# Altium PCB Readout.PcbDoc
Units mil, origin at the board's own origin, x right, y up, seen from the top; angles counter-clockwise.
Board outline 2000 x 2300 mil, 6 copper layers (Top Layer, VCC, GND, VEE, GND 2, Bottom Layer), stack 32.112 mil thick; 55 components, 25 nets, 158 pads, 32 vias.
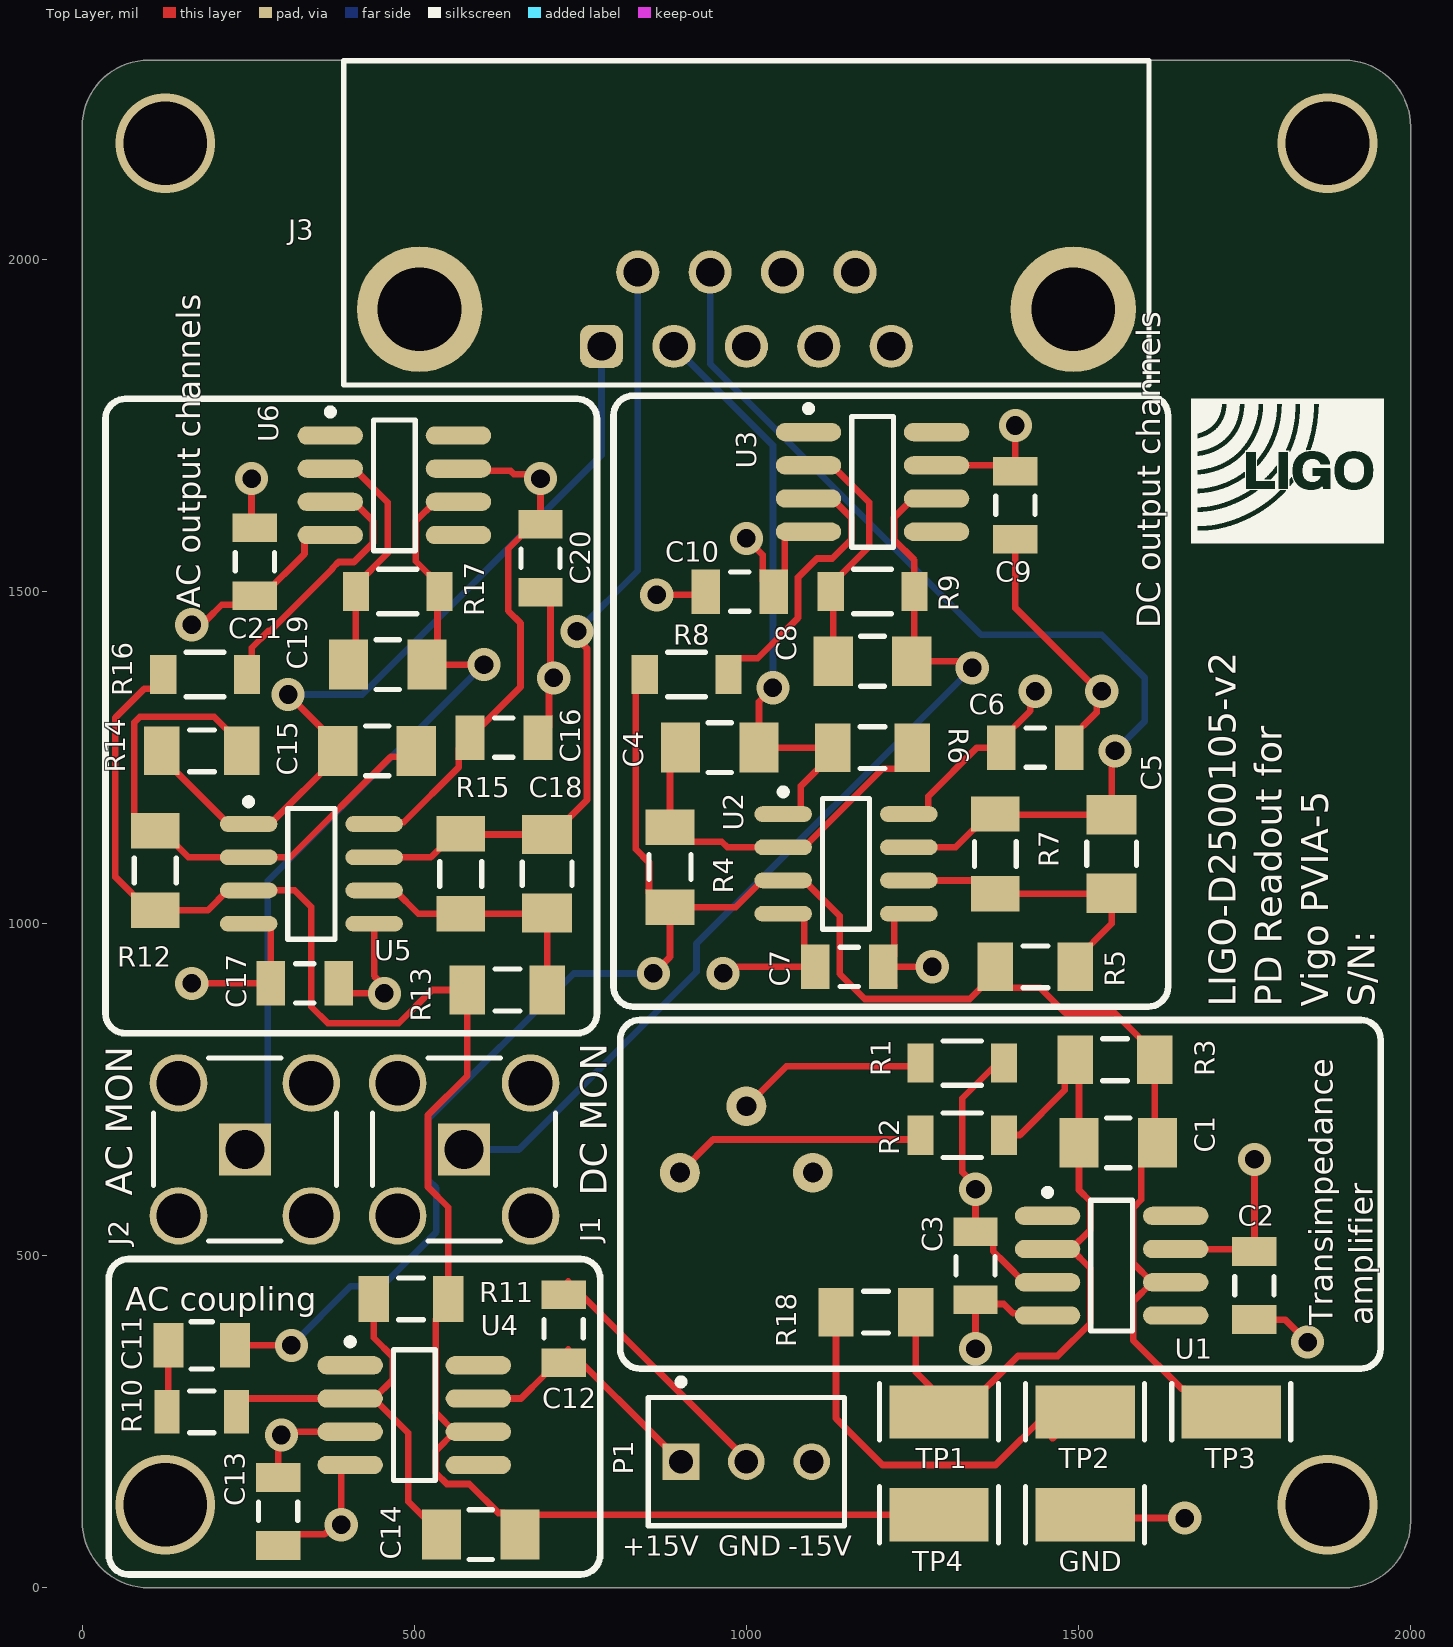
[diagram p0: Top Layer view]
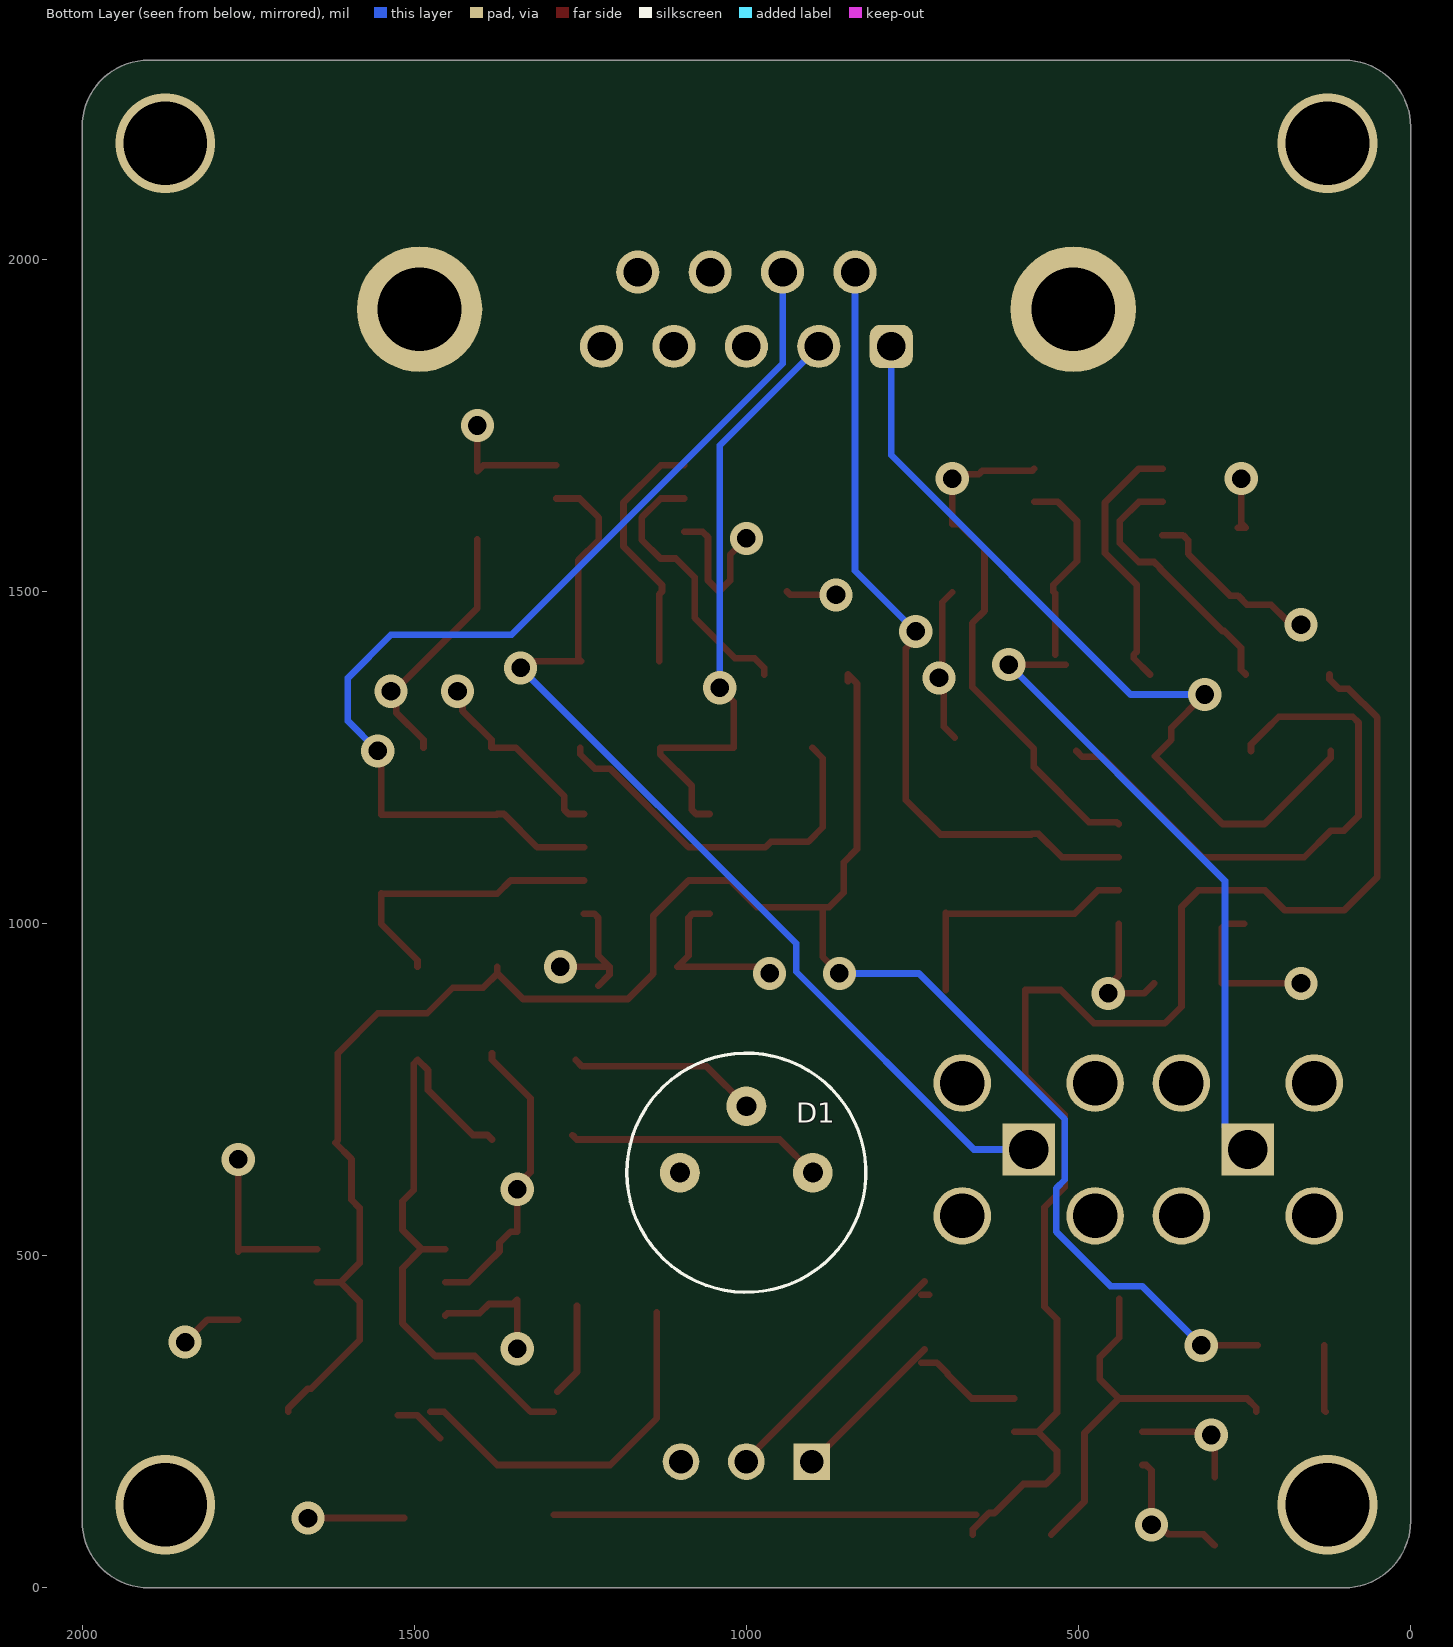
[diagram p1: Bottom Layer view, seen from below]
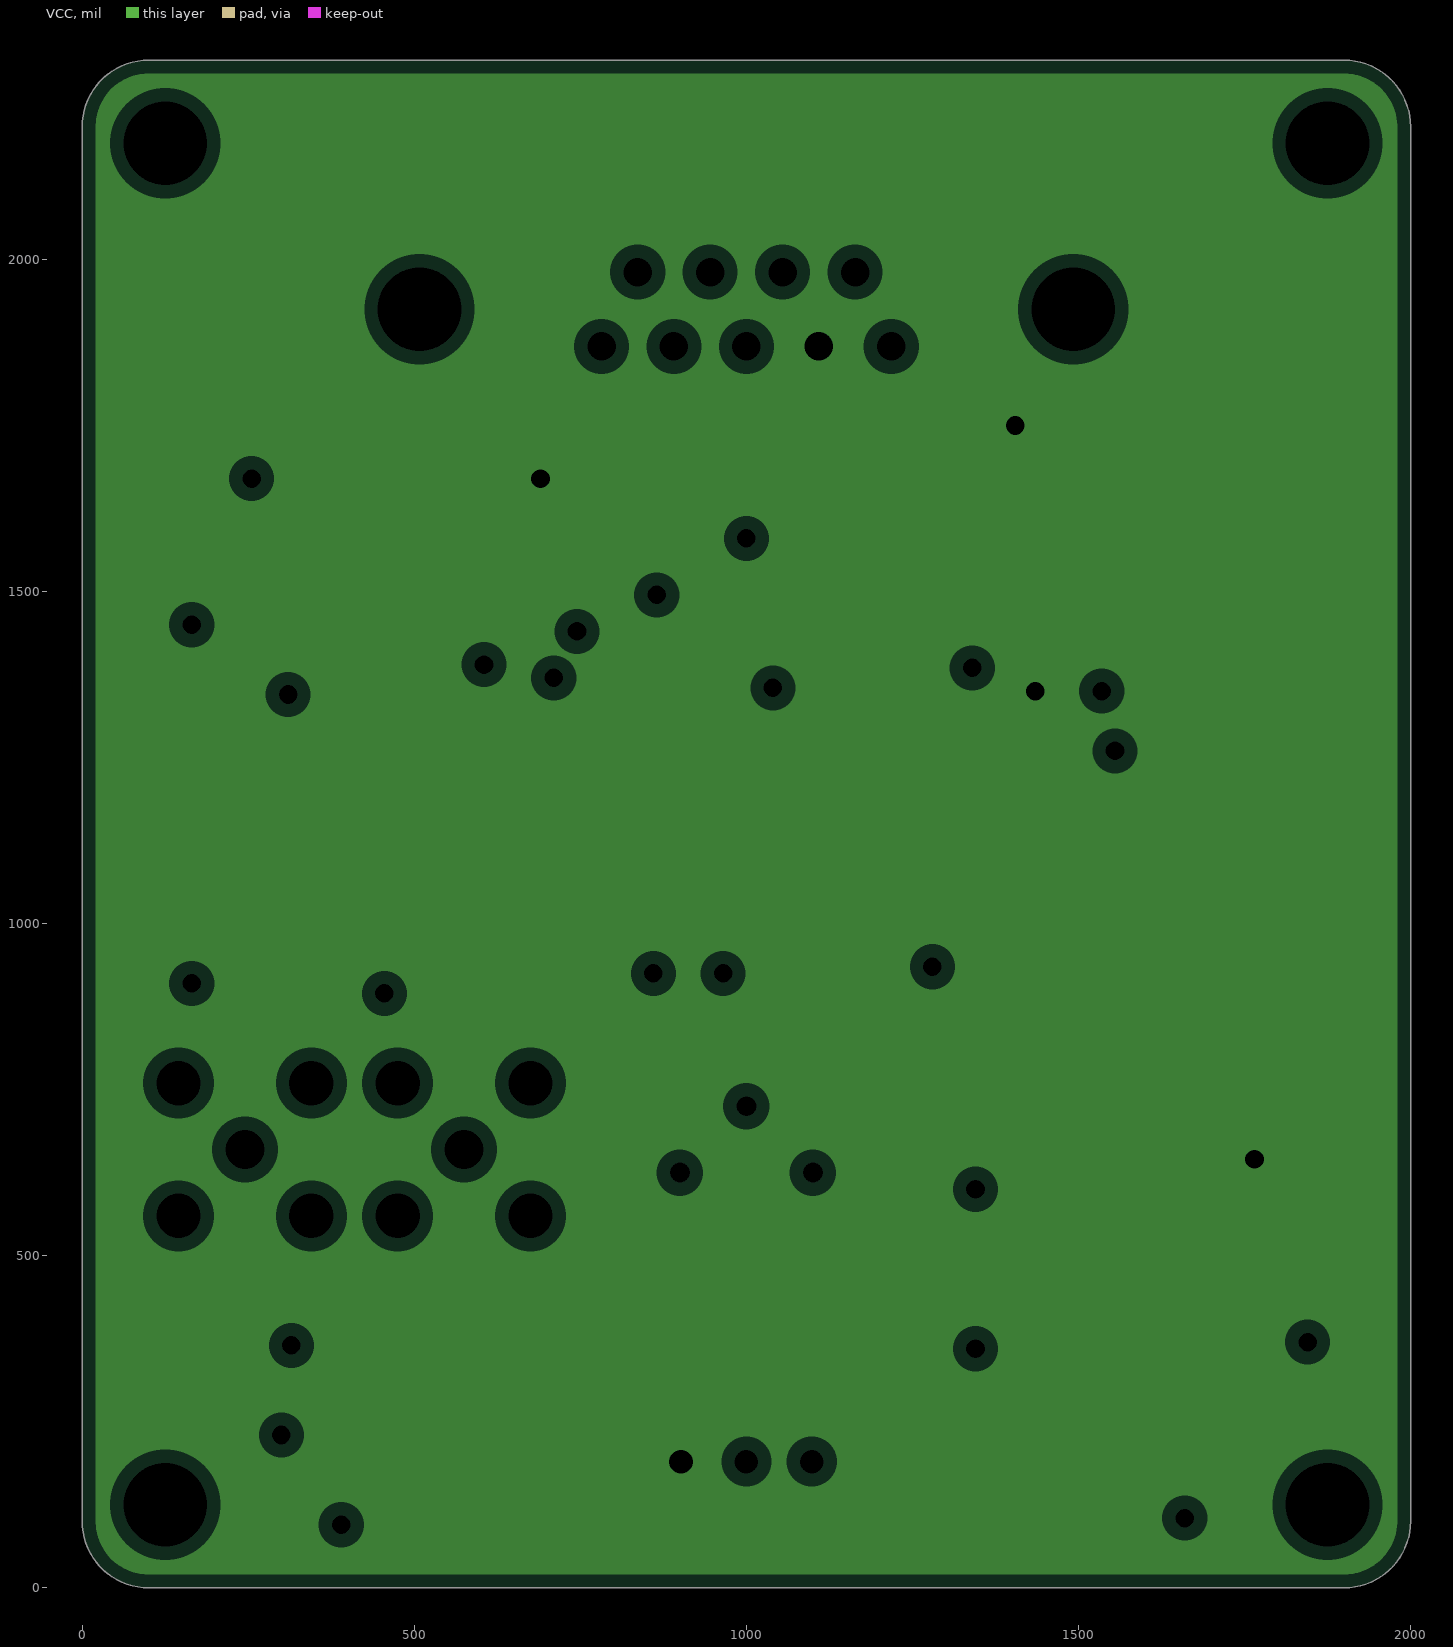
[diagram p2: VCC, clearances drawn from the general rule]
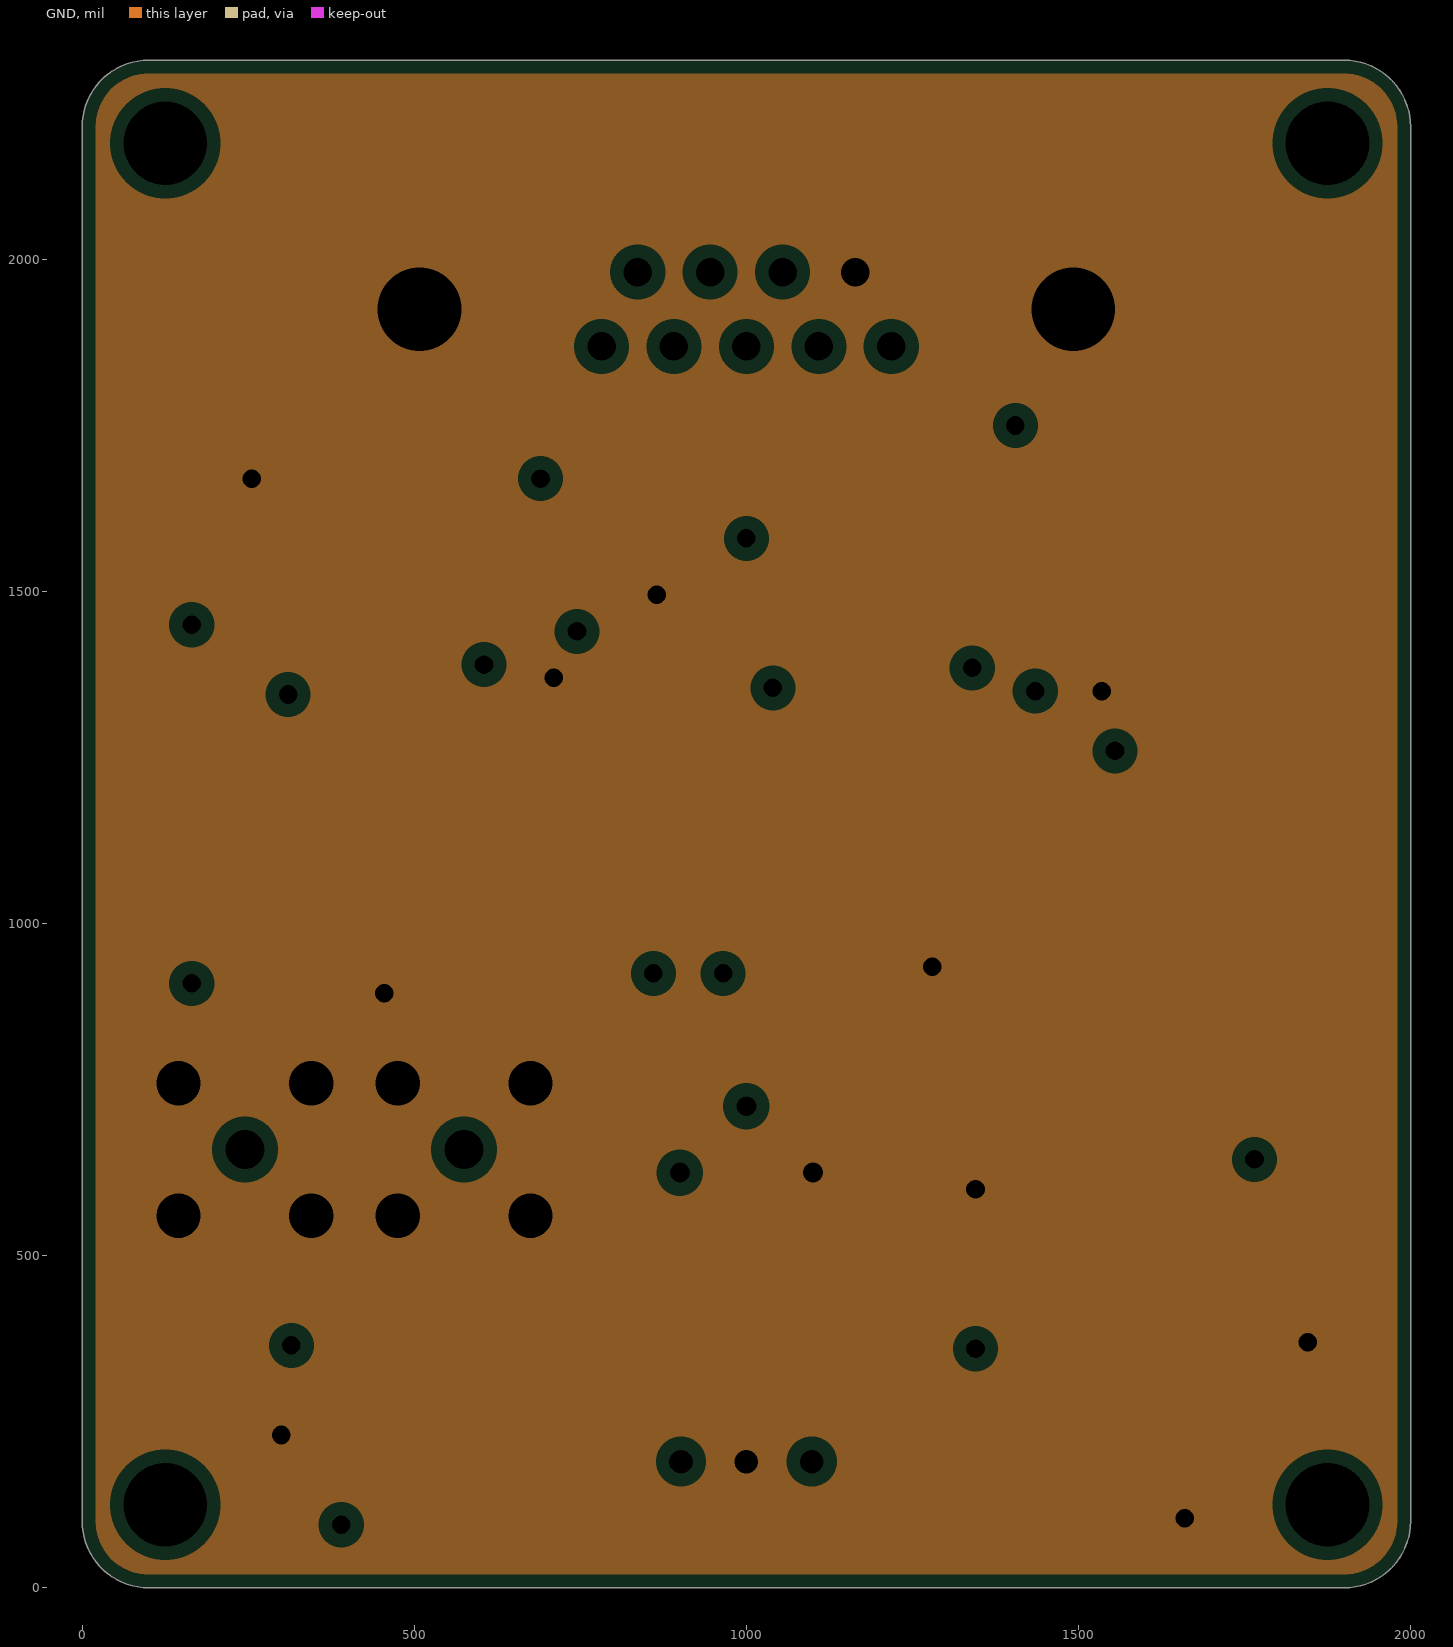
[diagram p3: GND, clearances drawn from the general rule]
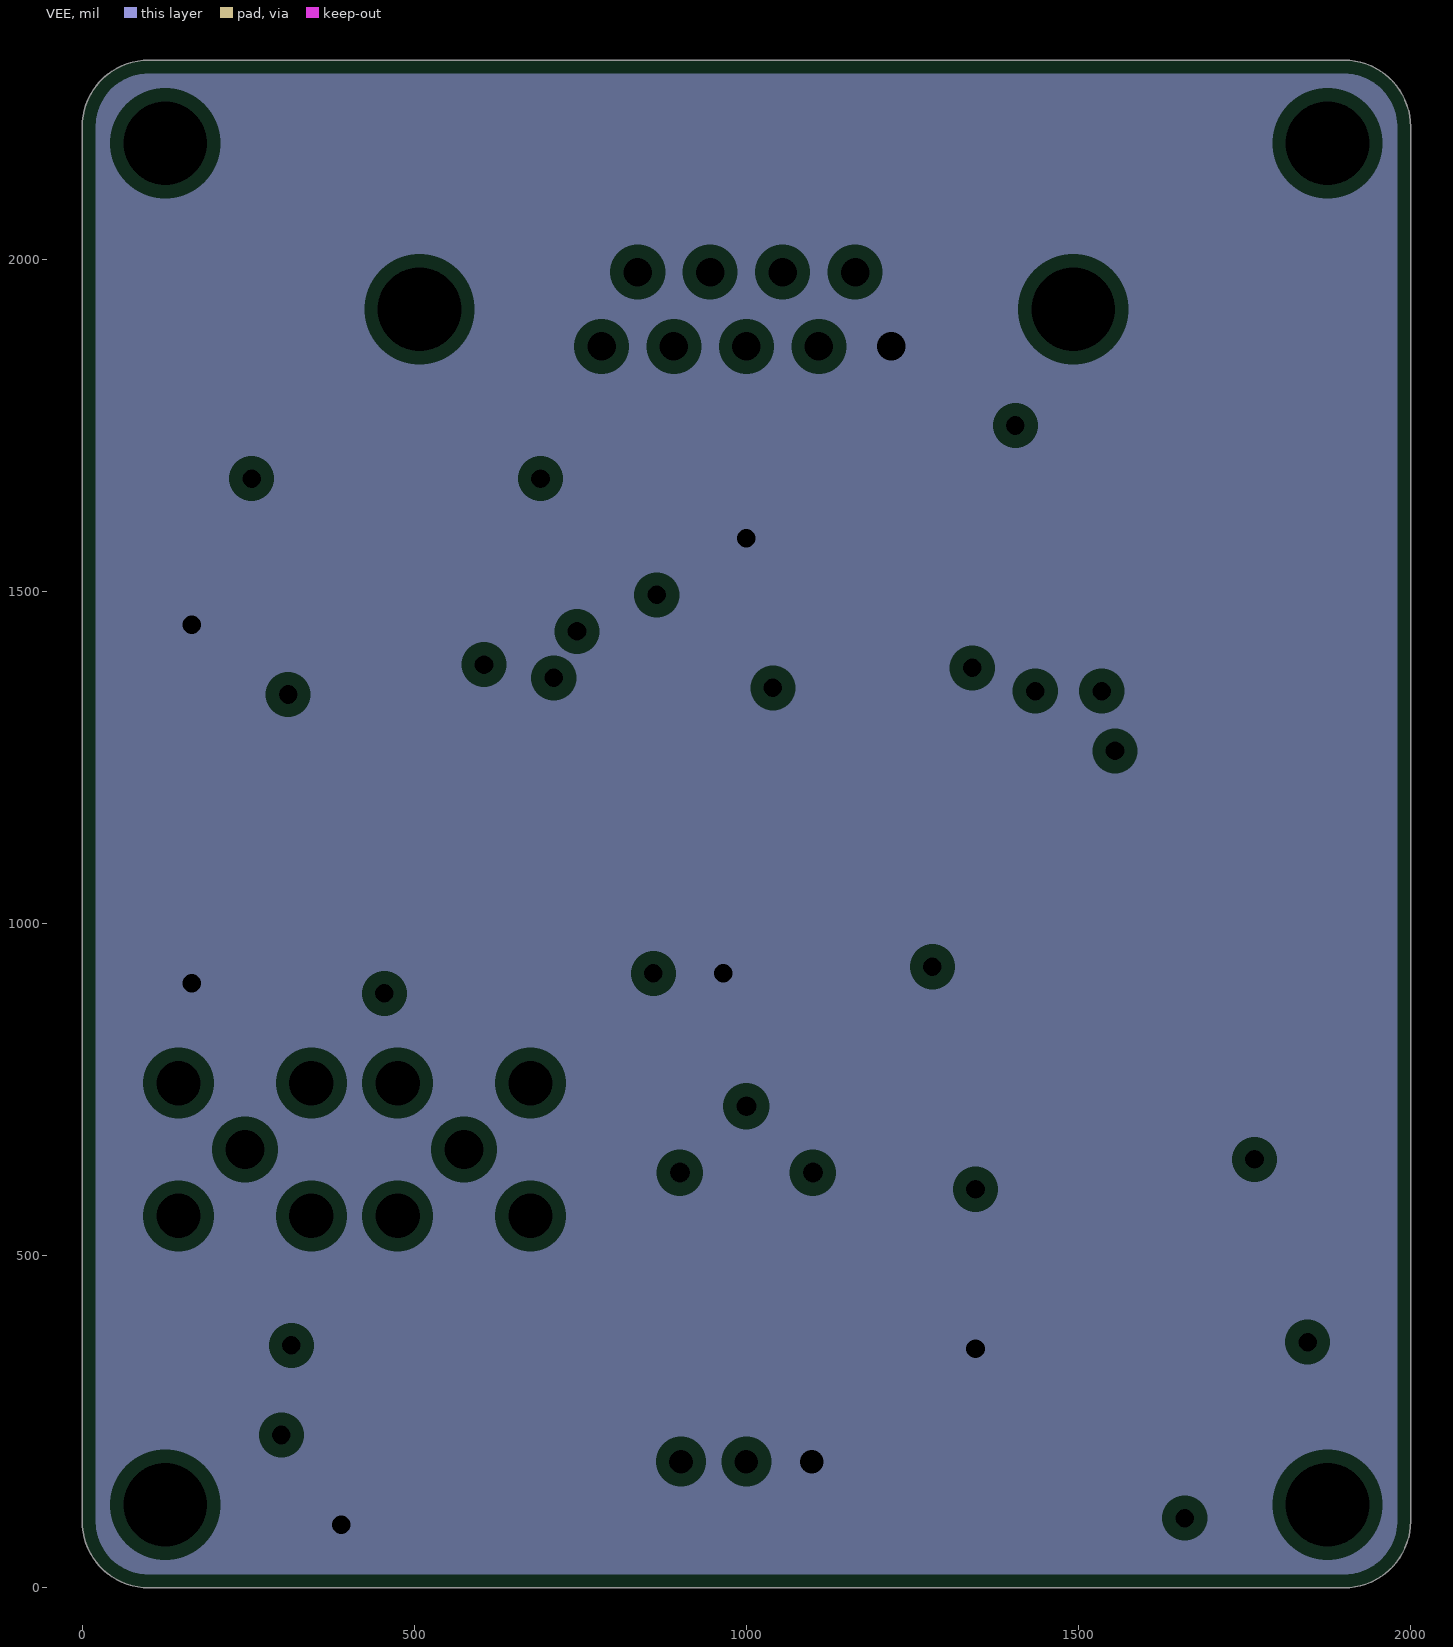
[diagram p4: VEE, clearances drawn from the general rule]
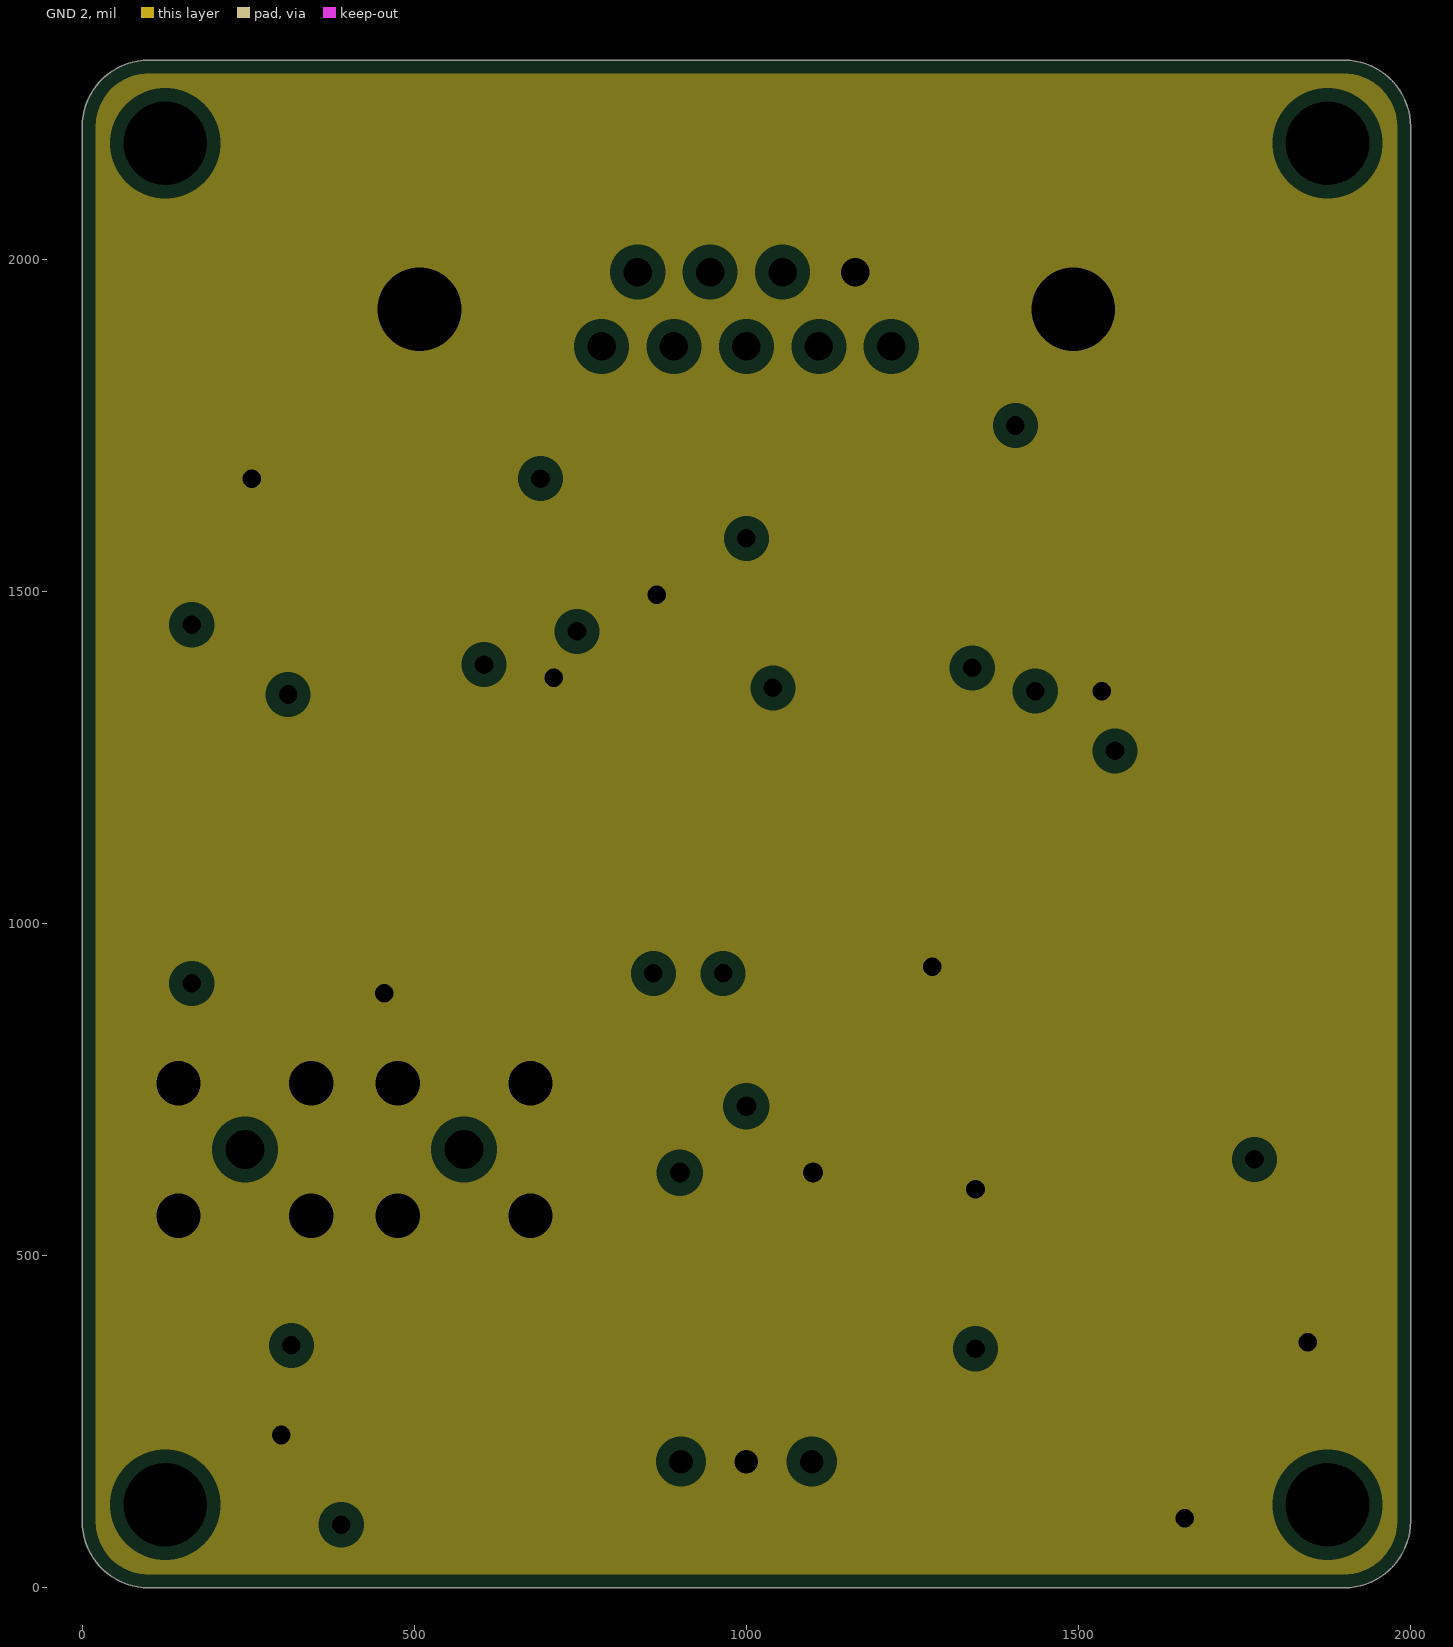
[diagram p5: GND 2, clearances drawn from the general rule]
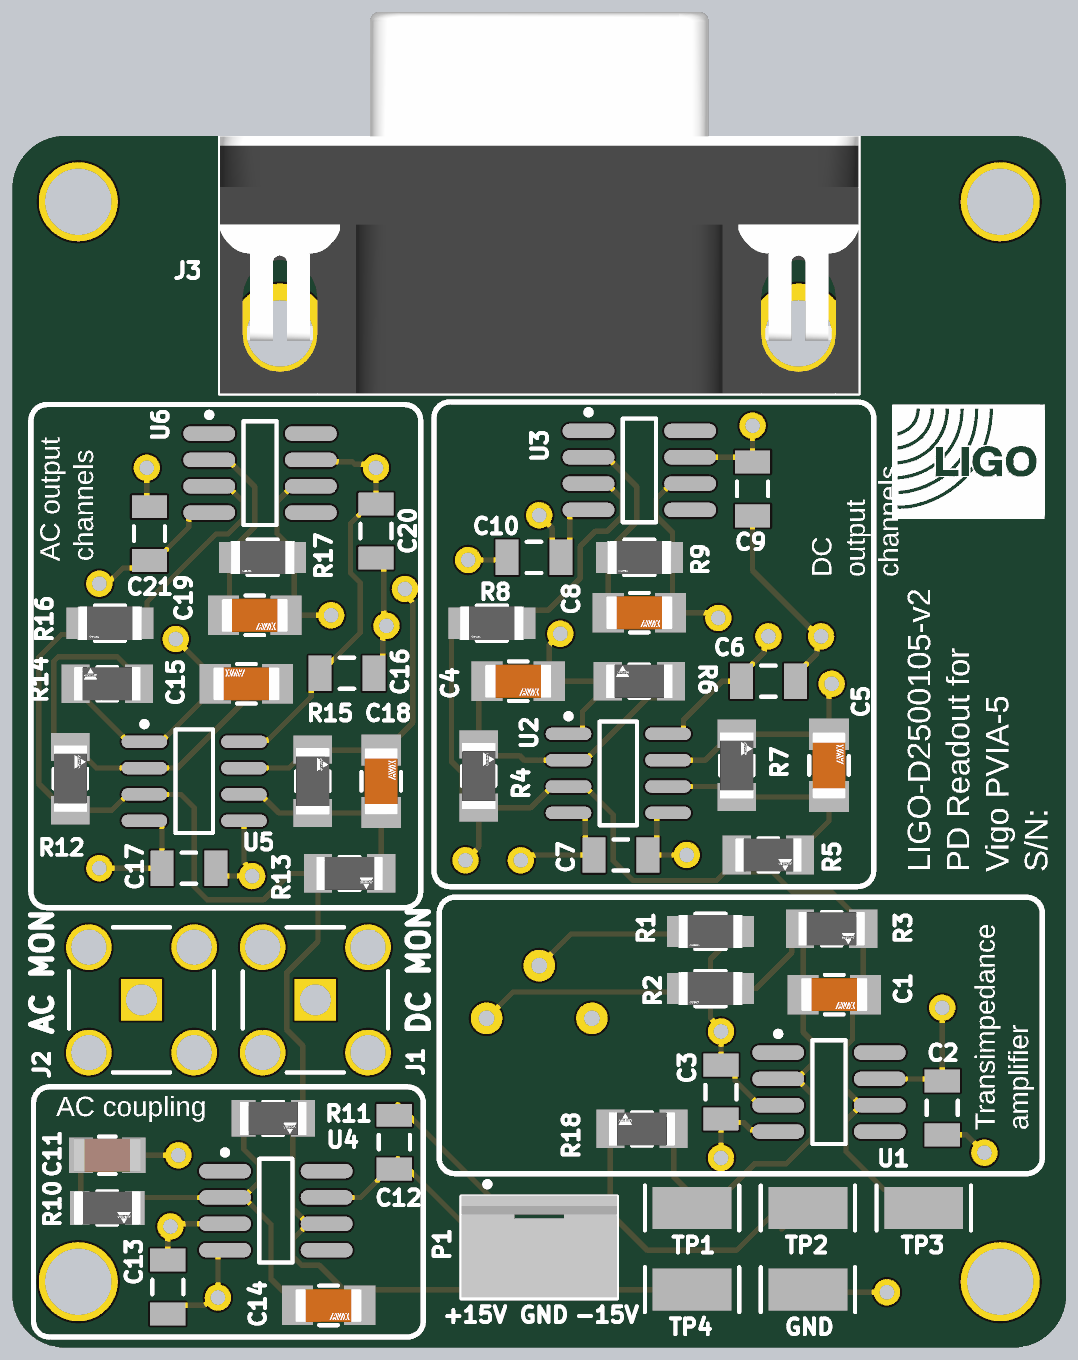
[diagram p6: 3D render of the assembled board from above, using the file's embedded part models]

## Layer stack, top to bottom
Top Solder: solder mask 0.4, Solder Resist, Dk 3.5
Top Layer: signal copper 1.4
Dielectric 2: prepreg 2.8, PP-006, Dk 4.1
VCC: plane copper 1.378, net VCC
Dielectric 4: prepreg 2.8, PP-006, Dk 4.1
GND: plane copper 1.378, net GND
Dielectric 1: dielectric 12.6, FR-4, Dk 4.8
VEE: plane copper 1.378, net VEE
Dielectric 5: prepreg 2.8, PP-006, Dk 4.1
GND 2: plane copper 1.378, net GND
Dielectric 3: prepreg 2.8, PP-006, Dk 4.1
Bottom Layer: signal copper 1.4
Bottom Solder: solder mask 0.4, Solder Resist, Dk 3.5

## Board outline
0,100 0,2200 cw(c100,2200) 100,2300 1900,2300 cw(c1900,2200) 2000,2200 2000,100 cw(c1900,100) 1900,0 100,0 cw(c100,100)

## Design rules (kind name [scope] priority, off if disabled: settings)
Clearance [All] p1: gap=10 ignorepadtopadclearanceinfootprint=FALSE
PlaneClearance [All] p1: clearance=20
PlaneConnect [All] p1: planeconnectstyle=Relief reliefexpansion=20 reliefentries=4 reliefconductorwidth=10 reliefairgap=10
PolygonConnect [All] p1: connectstyle=Relief reliefconductorwidth=10 reliefentries=4 polygonreliefangle="90 Angle" airgapwidth=10
RoutingVias [All] p1: holewidth=28 width=50 viastyle="Through Hole" minholewidth=28 minwidth=50 maxholewidth=28 maxwidth=50
SolderMaskExpansion [All] p1: expansion=4 istentingtop=FALSE
SupplyNets "Schematic Supply Nets_2" [InNet('GND')] p1: voltage=0.000
SupplyNets "Schematic Supply Nets_1" [InNet('VCC')] p2: voltage=0.000
SupplyNets "Schematic Supply Nets" [InNet('VEE')] p3: voltage=0.000
Width [All] p1: maxlimit=10 minlimit=10 preferedwidth=10
28 further rules are at their usual default settings.

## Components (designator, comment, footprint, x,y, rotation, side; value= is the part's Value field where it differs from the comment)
C1 "12061A470JAT2A" FP-1206-L_3_2_0_2-W_1_6_0-IPC_A 1560,670 r0 top
C2 "C1206C105K5RACTU" CAPC3216X110X50LL20T25 1765,455 r270 top
C3 "C1206C105K5RACTU" CAPC3216X110X50LL20T25 1345,485 r90 top
C4 "12061A470JAT2A" FP-1206-L_3_2_0_2-W_1_6_0-IPC_A 960,1265 r0 top
C5 "12061A470JAT2A" FP-1206-L_3_2_0_2-W_1_6_0-IPC_A 1550,1105 r90 top
C6 "C1206C105K5RACTU" CAPC3216X110X50LL20T25 1435,1265 r0 top
C7 "C1206C105K5RACTU" CAPC3216X110X50LL20T25 1155,935 r0 top
C8 "12061A470JAT2A" FP-1206-L_3_2_0_2-W_1_6_0-IPC_A 1190,1395 r0 top
C9 "C1206C105K5RACTU" CAPC3216X110X50LL20T25 1405,1630 r270 top
C10 "C1206C105K5RACTU" CAPC3216X110X50LL20T25 990,1500 r180 top
C11 "CL31A106KBHNNNE" FP-CL31-IPC_C 180,365 r180 top value=10uF
C12 "C1206C105K5RACTU" CAPC3216X110X50LL20T25 725,390 r90 top
C13 "C1206C105K5RACTU" CAPC3216X110X50LL20T25 295,115 r90 top
C14 "12065A4R7DAT2A" FP-1206-L_3_2_0_2-W_1_6_0-IPC_A 600,80 r0 top
C15 "12061A470JAT2A" FP-1206-L_3_2_0_2-W_1_6_0-IPC_A 444.09,1260 r180 top
C16 "C1206C105K5RACTU" CAPC3216X110X50LL20T25 635,1280 r0 top
C17 "C1206C105K5RACTU" CAPC3216X110X50LL20T25 335,910 r0 top
C18 "12061A470JAT2A" FP-1206-L_3_2_0_2-W_1_6_0-IPC_A 700,1075 r90 top
C19 "12061A470JAT2A" FP-1206-L_3_2_0_2-W_1_6_0-IPC_A 460,1390 r0 top
C20 "C1206C105K5RACTU" CAPC3216X110X50LL20T25 690,1550 r270 top
C21 "C1206C105K5RACTU" CAPC3216X110X50LL20T25 260,1545 r90 top
D1 "Vigo PVIA-5-1x1-TO39-NW-36" TO-39 1000,625 r180 bottom
GND "5019" FP-5019-MFG 1510,110 r0 top
J1 "901-144-8RFX" AMPH-901-144-8RFX_V 575,660 r90 top
J2 "901-144-8RFX" AMPH-901-144-8RFX_V 245,660 r90 top
J3 "618009211821" 618009211821 1000,2055 r180 top
P1 "171825-3" TECO-171825-3_V 1000,190 r0 top
R1 "RC1206JR-070RL" FP-RC1206-MFG 1325,790 r180 top value=0Ω
R2 "RC1206JR-070RL" FP-RC1206-MFG 1325,681.51 r180 top value=0Ω
R3 "CRCW12062K00FKEA" FP-CRCW1206-e3-IPC_A 1555,795 r0 top
R4 "CRCW12062K00FKEA" FP-CRCW1206-e3-IPC_A 885,1085 r90 top
R5 "CRCW12062K00FKEA" FP-CRCW1206-e3-IPC_A 1435,935 r0 top
R6 "CRCW12062K00FKEA" FP-CRCW1206-e3-IPC_A 1190,1265 r180 top
R7 "CRCW12062K00FKEA" FP-CRCW1206-e3-IPC_A 1375,1105 r90 top
R8 "RC1206JR-070RL" FP-RC1206-MFG 910,1375 r180 top value=0Ω
R9 "RC1206JR-070RL" FP-RC1206-MFG 1190,1500 r180 top value=0Ω
R10 "CRCW12061K50FKEA" FP-CRCW1206-e3-IPC_C 180,265 r0 top
R11 "CRCW1206150KFKEA" FP-CRCW1206-e3-IPC_B 495,435 r0 top
R12 "CRCW12062K00FKEA" FP-CRCW1206-e3-IPC_A 110,1080 r90 top
R13 "CRCW12062K00FKEA" FP-CRCW1206-e3-IPC_A 640,900 r0 top
R14 "CRCW12062K00FKEA" FP-CRCW1206-e3-IPC_A 180.08,1260 r180 top
R15 "CRCW12062K00FKEA" FP-CRCW1206-e3-IPC_A 570,1075 r90 top
R16 "RC1206JR-070RL" FP-RC1206-MFG 185,1375 r180 top value=0Ω
R17 "RC1206JR-070RL" FP-RC1206-MFG 475,1500 r180 top value=0Ω
R18 "CRCW12062K00FKEA" FP-CRCW1206-e3-IPC_A 1195,415 r180 top
TP1 "5019" FP-5019-MFG 1290,265 r180 top
TP2 "5019" FP-5019-MFG 1510,265 r0 top
TP3 "5019" FP-5019-MFG 1730,265 r180 top
TP4 "5019" FP-5019-MFG 1290,110 r180 top
U1 "LT1128CS8#PBF" LT-S8-8_M 1550,485 r0 top
U2 "AD8672ARZ" ADI-R-8_N 1150,1090 r0 top
U3 "OP27GSZ-REEL" ADI-R-8_M 1190,1665 r0 top
U4 "OP27GSZ-REEL" ADI-R-8_M 500,260 r0 top
U5 "AD8672ARZ" ADI-R-8_N 345,1075 r0 top
U6 "OP27GSZ-REEL" ADI-R-8_M 470,1660 r0 top

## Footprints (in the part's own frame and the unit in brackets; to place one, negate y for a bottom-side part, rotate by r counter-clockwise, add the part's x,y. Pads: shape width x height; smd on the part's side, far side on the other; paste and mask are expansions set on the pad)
618009211821 [mm] "09p 8.08mm bracket, board lock & UNC4-40 Rivet without hex screw"
  rrect50% 1.65x1.65 hole 1.09: 1(5.54,4.72)
  round 1.65 hole 1.09: 2(2.77,4.72) 3(0,4.72) 4(-2.77,4.72) 5(-5.54,4.72) 6(4.155,1.88) 7(1.385,1.88) 8(-1.385,1.88) 9(-4.155,1.88)
  round 4.8 hole 3.2: M1(-12.5,3.3) M2(12.5,3.3)
  silkscreen extent -15.4,-6.2 15.4,6.2, body extent -15.4,-12.2 15.4,6.2, height 12.55
ADI-R-8_M [mm] "SOIC, 8-Leads, Body 4.9x3.9mm, Pitch 1.27mm, IPC Low Density"
  oval 2.5x0.7 smd: 1(-2.45,1.905) 2(-2.45,0.635) 3(-2.45,-0.635) 4(-2.45,-1.905) 5(2.45,-1.905) 6(2.45,-0.635) 7(2.45,0.635) 8(2.45,1.905)
  silkscreen extent -2.57,-2.5 0.8,2.93, body extent -2,-2.5 2,2.5, height 1.75
ADI-R-8_N [mm] "SOIC, 8-Leads, Body 4.9x3.9mm, Pitch 1.27mm, IPC Medium Density"
  oval 2.2x0.6 smd: 1(-2.4,1.905) 2(-2.4,0.635) 3(-2.4,-0.635) 4(-2.4,-1.905) 5(2.4,-1.905) 6(2.4,-0.635) 7(2.4,0.635) 8(2.4,1.905)
  silkscreen extent -2.52,-2.5 0.9,2.88, body extent -2,-2.5 2,2.5, height 1.75
AMPH-901-144-8RFX_V [mm] "THD, 5-Leads, Body 7x7mm, Pitch 2.54mm"
  rect 2x2 hole 1.5: 1(0,0)
  round 2.2 hole 1.7: 2(-2.54,2.54) 3(-2.54,-2.54) 4(2.54,-2.54) 5(2.54,2.54)
  silkscreen extent -3.5,-3.5 3.5,3.5, body extent -3.55,-3.55 3.55,3.55, height 9.53
CAPC3216X110X50LL20T25 [mm] "Chip Capacitor, 2-Leads, Body 3.20x1.60mm, IPC High Density"
  rect 1.1x1.7 smd: 1(-1.3,0) 2(1.3,0)
  silkscreen extent -0.35,-0.75 0.35,0.75, body extent -1.7,-0.9 1.7,0.9, height 1.1
FP-1206-L_3_2_0_2-W_1_6_0-IPC_A [mil]
  rect 59.24x75.05 smd paste+0 mask+0: 1(-59.09,0) 2(59.09,0)
  silkscreen extent -18,-38 18,38, body extent -108,-57 108,57, height 10
FP-5019-MFG [mm]
  rect 3.8x2.03 smd paste+0 mask+0: 1(0,0)
  silkscreen extent -2.27,-1.08 2.27,1.08
FP-CL31-IPC_C [mil]
  rect 45.45x67.17 smd paste+0 mask+0: 1(-50.23,0) 2(50.23,0)
  silkscreen extent -16,-35 16,35, body extent -77,-39 77,39, height 10
FP-CRCW1206-e3-IPC_A [mil]
  rect 53.39x73.16 smd paste+0 mask+0: 1(-60.08,0) 2(60.08,0)
  silkscreen extent -19,-31 19,31, body extent -106,-56 106,56, height 10
FP-CRCW1206-e3-IPC_B [mil]
  rect 45.51x69.22 smd paste+0 mask+0: 1(-56.14,0) 2(56.14,0)
  silkscreen extent -19,-31 19,31, body extent -89,-44 89,44, height 10
FP-CRCW1206-e3-IPC_C [mil]
  rect 37.64x65.28 smd paste+0 mask+0: 1(-52.21,0) 2(52.21,0)
  silkscreen extent -19,-31 19,31, body extent -75,-38 75,38, height 10
FP-RC1206-MFG [mm]
  rect 1x1.5 smd paste+0 mask+0: 1(-1.6,0) 2(1.6,0)
  silkscreen extent -0.72,-0.85 0.72,0.85, body extent -2.2,-0.95 2.2,0.95, height 0.25
LT-S8-8_M [mm] "SOIC, 8-Leads, Body 4.9x3.9mm, Pitch 1.27mm, IPC Low Density"
  oval 2.5x0.7 smd: 1(-2.45,1.905) 2(-2.45,0.635) 3(-2.45,-0.635) 4(-2.45,-1.905) 5(2.45,-1.905) 6(2.45,-0.635) 7(2.45,0.635) 8(2.45,1.905)
  silkscreen extent -2.57,-2.5 0.8,2.93, body extent -2,-2.5 2,2.5, height 1.76
TECO-171825-3_V [mm] "Connector, 3-Leads, Body 4.9x7.5mm, Pitch 2.5mm"
  rect 1.4x1.4 hole 0.9: 1(-2.5,0)
  round 1.4 hole 0.9: 2(0,0) 3(2.5,0)
  silkscreen extent -3.75,-2.45 3.75,3.17, body extent -3.75,-2.4 3.75,2.5, height 10.4
TO-39 [mil]
  round 60 hole 30: 1(0,100) 2(100,0) 3(-100,0)
  silkscreen extent -180,-180 180,180

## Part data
C1: library part CMP-04427-018828-1, "General Purpose Ceramic Capacitor, 1206, 47pF, 5%, NP0, 30ppm/°C, 100V", Capacitance=47pF, Case Code (Imperial)=1206, Case Code (Metric)=3216, Dielectric=C0G, Insulation Resistance=100GR, Max Operating Temperature=125°C, Min Operating Temperature=-55°C, Package Quantity=1, Temperature Coefficient=30ppm/°C, Tolerance=5%, Voltage=100V
C2 C3 C6 C7 C9 C10 C12 C13 C16 C17 C20 C21: library part CMP-2000-06011-1, "Chip Capacitor, 1 uF, +/- 10%, 50 V, -55 to 125 degC, 1206 (3216 Metric), RoHS, Tape and Reel", Capacitance=1uF, Capacitance - nF=1000nF, Case Code - in=1206, Case Code - mm=3216, Case Height=1mm, Case Length=3.2mm, Case Width=1.6mm, Dielectric=X7R, Manufacturer=Kemet, Maximum Operating Temperature=+125C, Minimum Operating Temperature=-55C, Operating Temperature Range=-55Cto+125C, Package / Case=1206(3216metric), Package Description="2-Pin Surface Mount Device, Body 3.2 x 1.6 mm", Temperature Coefficient / Code=+/-15%, Tolerance=10%, Voltage Rating=50V
C4 C5 C8 C15 C18 C19: library part CMP-04427-018828-1, "General Purpose Ceramic Capacitor, 1206, 47pF, 5%, NP0, 30ppm/°C, 100V", Capacitance=omit, Case Code (Imperial)=1206, Case Code (Metric)=3216, Dielectric=C0G, Insulation Resistance=100GR, Max Operating Temperature=125°C, Min Operating Temperature=-55°C, Package Quantity=1, Temperature Coefficient=30ppm/°C, Tolerance=5%, Voltage=100V
C11: library part CMP-13271-000014-1, "CAP CER 3.3UF 25V X7R 1206", Capacitance=10uF, Manufacturer=Samsung, Manufacturer Part Number=CL31B335KAHVPNE, Package=CL31, Temperature="-55°C to +125°C", Temperature Characteristic=X7R, Temperature Coefficient=15%, Temperature Range High=+125°C, Temperature Range Low=-55°C, Tolerance=10%, Voltage Rating=25V
C14: library part CMP-04427-018828-1, "General Purpose Ceramic Capacitor, 1206, 47pF, 5%, NP0, 30ppm/°C, 100V", Capacitance=4.7pF, Case Code (Imperial)=1206, Case Code (Metric)=3216, Dielectric=C0G, Insulation Resistance=100GR, Max Operating Temperature=125°C, Min Operating Temperature=-55°C, Package Quantity=1, Temperature Coefficient=30ppm/°C, Tolerance=5%, Voltage=100V
D1: library part Photodiode, "Photodiode"
GND TP1 TP2 TP3 TP4: library part CMP-1672-00008-2
J1 J2: library part CMP-2000-05706-1, "Coaxial Connector, 18 GHz, 50 Ohm, -65 to 165 degC, 5-Pin THD, RoHS, Bulk", Dielectric Material=Polytetrafluoroethylene(PTFE), Frequency - Max=18GHz, Housing Color=Gold, Manufacturer=Amphenol, Operating Temperature=-65°C~165°C, Package Description="5-Pin Through Hole Device, Body 7 x 7 mm, Pitch 2.54 mm", Standard Package=1, Voltage Rating=-
J3: library part CMP-1502-00208-2, Contact Resistance=30mΩ, Current Rating=3A, Insulation Resistance=5GΩ, Max Operating Temperature=105°C, Min Operating Temperature=-55°C, Operating Supply Voltage=125V
P1: library part CMP-2000-07494-1, "Male Header, Pitch 2.5 mm, 1 x 3 Position, Height 10.4 mm, Tail Length 3.6 mm,  / -20 to 95 degC / , RoHS, Bulk", Colour=Natural, Contact Resistance=20mOhm, Flammability Rating=UL94V-0, Manufacturer="TE Connectivity", Max Current Rating=3.5A, Max Operating Temperature=95degC, Max Voltage Rating (AC)=250V, Max Voltage Rating (DC)=350.25kV, Min Operating Temperature=-20degC, Package Description="Male Header, Pitch 2.5 mm, 1 x 3 Position, Height 10.4 mm, Tail Length 3.6 mm", Package Quantity=1000, Voltage Rating=350V
R1 R2 R8 R9 R16 R17: library part CMP-2100-03681-2, "RES SMD 0 OHM JUMPER 1/4W 1206", Manufacturer=YAGEO, Package=RC1206, Power Rating=0.25W, Resistance=0Ω, Temperature="-55°C to +155°C", Temperature Coefficient=300ppm/°C, Temperature Range High=+155°C, Temperature Range Low=-55°C, Tolerance=5%, Voltage Rating=200V
R3 R4 R5 R6 R7 R12 R13 R14 R15 R18: library part CMP-1014-00542-3, "RES Thick Film, 2kΩ, 1%, 0.25W, 100ppm/°C, 1206", Case Code (Imperial)=1206, Case Code (Metric)=3216, Max Operating Temperature=155°C, Max Power Dissipation=250mW, Min Operating Temperature=-55°C, Package Quantity=10, Resistance=2kR, Temperature Coefficient=100ppm/°C, Tolerance=1%, Voltage Rating=200V
R10: library part CMP-02407-002229-1, "RES Thick Film, 1.5kΩ, 1%, 0.25W, 100ppm/°C, 1206", Case Code (Imperial)=1206, Case Code (Metric)=3216, Max Operating Temperature=155°C, Max Power Dissipation=250mW, Min Operating Temperature=-55°C, Package Quantity=10, Resistance=1.5kR, Temperature Coefficient=100ppm/°C, Tolerance=1%, Voltage Rating=200V
R11: library part CMP-2003-01810-2, "RES Thick Film, 150kΩ, 1%, 0.25W, 100ppm/°C, 1206", Case Code (Imperial)=1206, Case Code (Metric)=3216, Max Operating Temperature=155°C, Max Power Dissipation=250mW, Min Operating Temperature=-55°C, Package Quantity=10, Resistance=150kR, Temperature Coefficient=100ppm/°C, Tolerance=1%, Voltage Rating=200V
U1: library part CMP-0359-03002-2, "Single Channel, Low Noise High Speed Operational Amplifier, 20 MHz Typical GBW, 6 V/us Typical SR, 8 to 44 V, 8-Pin SOIC (S8-8), Commercial, Pb-Free", Linear Technology Part Number=LT1128, Manufacturer="Linear Technology"
U2 U5: library part CMP-0384-00608-2, "Double Channel Wide Bandwidth Operational Amplifier, 10 MHz BW, 4 V/us SR, Industrial, 8-pin SOIC (R-8), Tube", Amplifiers Per Package=2, Generic Part Number=AD8672, Input Bias Current=3nA, Input Offset Voltage=20uV, Manufacturer="Analog Devices"
U3 U4 U6: library part CMP-0384-01390-1, "Single Channel Low Noise Operational Amplifier, 8 MHz BW, 2.8 V/us SR, Industrial, 8-pin SOIC (R-8), Reel", Amplifiers Per Package=1, Generic Part Number=OP27, Input Bias Current=15nA, Input Offset Voltage=30uV, Manufacturer="Analog Devices"

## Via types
v1: diameter 50, hole 28, Top Layer to Bottom Layer, 28 vias
v2: diameter 150, hole 126, Top Layer to Bottom Layer, 4 vias

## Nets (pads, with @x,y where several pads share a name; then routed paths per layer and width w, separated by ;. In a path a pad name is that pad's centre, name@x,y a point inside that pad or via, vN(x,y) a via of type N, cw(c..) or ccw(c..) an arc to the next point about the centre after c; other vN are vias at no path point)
GND: C2.2 C3.2 C6.2 C7.2 C9.2 C10.2 C12.2 C13.2 C16.2 C17.2 C20.2 C21.2 D1.3 GND.1 J1.2 J1.3 J1.4 J1.5 J2.2 J2.3 J2.4 J2.5 J3.9 J3.M1 J3.M2 P1.2 R1.1 U1.3 U2.5 U4.3 U5.5 | length 2446.1
  Top Layer w10: v1(255,1670) 255,1602.99 248.19,1596.18 C21.2 ; C13.2 295,225 305,235 U4.3 ; C17.2 401.18,895 v1(455,895) 455,905.82 439.49,921.34 U5.5 ; C16.2 702.83,1296.65 702.83,1362.83 v1(710,1370) 705,1375 705,1483.82 C20.2 ; C12.2 C12.2@736.81,441.18 ; C12.2@731.81,461.18 1000,192.99 P1.2 ; v1(865,1495) 933.82,1495 C10.2 ; C7.2@1222.83,906.54 1206.18,923.19 C7.2 ; U2.5 1229.13,1015 1222.83,1008.71 1222.83,951.65 C7.2 ; v1(1280,935) C7.2 ; R1.1@1382.99,805 1382.99,795.16 1325,737.17 1325,625.86 1345,605.86 C3.2 1354.98,536.18 1371.63,519.53 1371.63,506.48 1389.33,488.78 1418.11,460 U1.3 ; C9.2 1405,1475 1530,1350 v1(1535,1350) 1527.35,1342.35 1527.35,1317.98 1486.18,1276.81 C6.2 ; GND.1@1515,105 v1(1660,105) ; C2.2 1811.18,403.82 v1(1845,370)
  other v1: 300,230 1345,600
NetC1_1: C1.1 R2.1 R3.1 R18.1 TP1.1 U1.2 | length 1070.1
  Top Layer w10: R18.1@1255.08,424.89 R18.1 1255.08,324.92 TP1.1@1285,295 ; TP1.1 1324.84,265 1408.86,349.02 1468.7,349.02 1517.76,398.08 1517.76,481.22 U1.2@1488.98,510 ; R2.1@1382.99,675 1389.81,681.82 1411.82,681.82 1479.28,749.28 1479.28,779.36 R3.1 1500.91,789 C1.1 1500.91,598.92 1517.76,582.08 1517.76,538.78 U1.2@1488.98,510 ; U1.2 U1.2@1488.98,510
NetC1_2: C1.2 C11.1 R3.2 R4.1 R5.1 R8.2 TP3.1 U1.6 U2.3 | length 3093.1
  Top Layer w10: C11.1 v1(315,365) ; R8.2@847.01,1365.16 R8.2 833.42,1361.41 833.42,1112.17 853.42,1092.17 853.42,1046.61 875.11,1024.92 R4.1 ; v1(860,925) 885,950 R4.1 ; R5.1 R5.1@1374.92,925.11 ; U1.6 U1.6@1611.02,460 ; TP3.1@1690,265 1690,270.16 1660.2,299.96 1655.04,299.96 1582.24,372.76 1582.24,431.22 U1.6@1611.02,460 ; R4.1 983.93,1024.92 1024.02,1065 U2.3 1087.01,1065 1140.47,1011.54 1140.47,924.38 1178.31,886.54 1336.34,886.54 R5.1@1374.92,925.11 ; R5.1@1374.92,925.11 1396.61,903.42 1442.17,903.42 1480.6,865 1554.97,865 1615.08,804.89 R3.2 1615.08,674 C1.2 1594.47,645.38 1594.47,584.14 1582.24,571.92 1582.24,488.78 U1.6@1611.02,460
  Bottom Layer w10: v1(315,365) 404.25,454.25 451.71,454.25 533.31,535.85 533.31,601.74 520.63,614.42 520.63,705.58 740.05,925 v1(860,925)
NetC4_1: C4.1 R4.2 R6.1 U2.2 | length 572
  Top Layer w10: C4.1 885,1249.09 R4.2 906.69,1123.39 962.96,1123.39 971.35,1115 U2.2 1087.01,1115 1205.43,1233.42 1228.39,1233.42 1250.08,1255.11 R6.1
NetC4_2: C4.2 J3.2 R6.2 U2.1 | length 928.1
  Top Layer w10: v1(1040,1355) 1019.09,1334.09 C4.2 R6.2 1129.92,1255.11 1082.01,1207.2 1082.01,1171.29 1075.72,1165 U2.1
  Bottom Layer w10: J3.2 1040,1720.12 v1(1040,1355)
NetC5_1: C5.1 R5.2 R7.1 U2.6 | length 447.9
  Top Layer w10: U2.6 1354.92,1065 R7.1 1549,1044.92 C5.1 1550,999.8 1495.08,944.89 R5.2
NetC5_2: C5.2 J3.7 R7.2 U2.7 | length 1541.8
  Top Layer w10: U2.7 1315.03,1115 1365.11,1165.08 R7.2 1376,1164.09 C5.2 1550,1255 v1(1555,1260)
  Bottom Layer w10: J3.7 945.47,1842.93 1353.4,1435 1535,1435 1600,1370 1600,1305 v1(1555,1260)
NetC8_1: C8.1 R9.2 U3.2 | length 379.3
  Top Layer w10: U3.2 1128.98,1690 1185,1633.98 1185,1567.83 1127.01,1509.84 R9.2 1130.91,1496.09 C8.1
NetC8_2: C8.2 J1.1 R9.1 U3.6 | length 1492.8
  Top Layer w10: U3.6 1251.02,1640 1222.24,1611.22 1222.24,1578.08 1252.99,1547.33 R9.1 1252.99,1398.91 C8.2 v1@1345,1395
  Bottom Layer w10: J1.1 657.46,660 925,927.54 925,970 v1(1340,1385)
NetC11_2: C11.2 R10.1 | length 100.8
  Top Layer w10: R10.1 129.77,266.98 C11.2
NetC14_1: C14.1 R10.2 R11.1 U4.2 | length 639.8
  Top Layer w10: R10.2 232.21,271.18 246.03,285 U4.2 U4.2@438.98,285 ; R11.1 438.86,376.41 467.76,347.51 467.76,313.78 U4.2@438.98,285 ; C14.1 490.91,130 490.91,233.06 U4.2@438.98,285
NetC14_2: C14.2 R11.2 R12.1 R13.1 R16.2 TP4.1 U4.6 U5.3 | length 2734.9
  Top Layer w10: R16.2 122.01,1368.05 107.32,1353.37 93.21,1353.37 50,1310.16 50,1070.03 100.11,1019.92 R12.1 188.93,1019.92 219.02,1050 U5.3 320.08,1050 344.96,1025.11 344.96,874.89 369.85,850 476.57,850 526.57,900 R13.1 579.92,771.06 520.63,711.77 520.63,603.45 551.14,572.94 R11.2 551.14,423.15 532.24,404.25 532.24,263.78 U4.6@561.02,235 ; U4.6 U4.6@561.02,235 ; C14.2@654.09,110 TP4.1 ; C14.2 659.09,87.9 634.47,112.52 626.56,112.52 582.87,156.22 549.1,156.22 532.24,173.08 532.24,206.22 U4.6@561.02,235
NetC15_1: C15.1 R12.2 R14.1 U5.2 | length 850.3
  Top Layer w10: R14.1 240.16,1269.89 218.47,1291.58 198.47,1311.58 87.09,1311.58 78.31,1302.79 78.31,1161.89 100.11,1140.08 R12.2 119.89,1140.08 159.97,1100 U5.2 313.36,1100 464.41,1251.06 494.23,1251.06 C15.1
NetC15_2: C15.2 J3.1 R14.2 U5.1 | length 1267.6
  Top Layer w10: R14.2 120,1250.11 220.11,1150 U5.1 282.9,1150 385,1252.1 360.38,1276.71 360.38,1294.62 v1(310,1345)
  Bottom Layer w10: v1(310,1345) 421.57,1345 781.89,1705.32 J3.1
NetC18_1: C18.1 R13.2 R15.1 U5.6 | length 391.4
  Top Layer w10: U5.6 470.98,1050 506.07,1014.92 R15.1 699,1014.92 C18.1 700.08,1015.83 R13.2
NetC18_2: C18.2 J3.6 R15.2 U5.7 | length 1195.9
  Top Layer w10: U5.7 525.03,1100 560.11,1135.08 R15.2 571,1134.09 C18.2 707.9,1134.09 760,1186.18 760,1414.18 745,1429.18 v1(745,1440)
  Bottom Layer w10: v1(745,1440) 836.42,1531.42 J3.6
NetC19_1: C19.1 R17.2 U6.2 | length 398.6
  Top Layer w10: U6.2 408.98,1685 460,1633.98 460,1557.83 412.01,1509.84 R17.2 412.01,1409.82 416.83,1405 416.83,1399.62 C19.1@392.21,1375
NetC19_2: C19.2 J2.1 R17.1 U6.6 | length 1258.4
  Top Layer w10: C19.2 v1(605,1390) ; C19.2@535,1405 535,1497.01 R17.1 537.99,1509.84 502.24,1545.59 502.24,1606.22 531.02,1635 U6.6
  Bottom Layer w10: J2.1 279.37,694.37 279.37,1064.37 v1(605,1390)
NetD1_1: D1.1 R1.2 | length 286.3
  Top Layer w10: D1.1 1060,785 1247.32,785 1257.01,794.69 R1.2@1257.01,795.16
NetD1_2: D1.2 R2.2 | length 385.4
  Top Layer w10: D1.2 950,675 1255.5,675 R2.2
NetR8_1: R8.1 U3.3 | length 419.6
  Top Layer w10: R8.1 972.99,1384.84 987.68,1399.53 1017.04,1399.53 1077.83,1460.32 1077.83,1521.25 1106.25,1549.67 1129.34,1549.67 1157.76,1578.08 1157.76,1611.22 1128.98,1640 U3.3
NetR16_1: R16.1 U6.3 | length 401
  Top Layer w10: R16.1 255.25,1382.26 255.25,1415.25 280.6,1440.6 283.11,1440.6 377.32,1534.81 377.32,1535.74 386.11,1544.53 409.2,1544.53 437.76,1573.08 437.76,1606.22 408.98,1635 U6.3
NetR18_2: R18.2 TP2.1 | length 641.6
  Top Layer w10: R18.2 1134.92,255.08 1205,185 1375.16,185 1455.16,265 TP2.1@1475.86,265 ; 1460.9,225.04 1495.86,260 1510,260 TP2.1@1525,260
VCC: C2.1 C6.1 C9.1 C12.1 C16.1 C20.1 J3.4 P1.1 U1.7 U2.8 U3.7 U4.7 U5.8 U6.7 | length 1952.4
  Top Layer w10: U5.8 442.09,1152.61 484.13,1152.61 567.17,1235.64 567.17,1263.35 C16.1 660,1356.18 660,1452.49 641.54,1470.95 641.54,1564.53 678.19,1601.18 C20.1 v1(690,1670) 683.36,1676.64 650,1676.64 645,1681.64 569.82,1681.64 U6.7 ; U4.7 660.67,285 696.54,320.87 696.54,322.17 713.19,338.82 C12.1 C12.1@736.81,338.82 ; C12.1@731.81,358.82 878.07,212.56 879.02,212.56 P1.1 ; U2.8 1267.68,1165 1273.98,1171.29 1273.98,1191.81 1347.17,1265 C6.1 1383.82,1276.81 1427.35,1320.34 1427.35,1342.35 v1(1435,1350) ; U3.7 1396.18,1690 C9.1 v1(1405,1750) ; U1.7 1761.18,510 C2.1 v1(1765,645)
VEE: C3.1 C7.1 C10.1 C13.1 C17.1 C21.1 J3.5 P1.3 U1.4 U2.4 U3.4 U4.4 U5.4 U6.4 | length 1386.4
  Top Layer w10: v1(165,910) C17.1 283.82,993.71 277.53,1000 U5.4 ; v1(165,1450) 175.82,1450 183.48,1457.65 187.65,1457.65 210,1480 246.18,1480 C21.1 271.81,1493.82 334.75,1556.76 334.75,1576.89 342.86,1585 U6.4 ; C13.1 311.65,80.47 364.65,80.47 379.18,95 v1(390,95) 390,176.89 398.11,185 U4.4 ; v1(965,925) 975,935 C7.1 1087.17,951.65 1087.17,1008.71 1080.87,1015 U2.4 ; v1(1000,1580) 1024.53,1555.47 1024.53,1516.65 C10.1 1057.83,1516.65 1057.83,1581.89 1065.95,1590 U3.4 ; v1@1345,370 C3.1 1351.43,427.39 1387.61,427.39 1401.64,413.36 1450.18,413.36 U1.4
  other v1: 1345,360
pads on no net: J3.3 J3.8 U1.1 U1.5 U1.8 U3.1 U3.5 U3.8 U4.1 U4.5 U4.8 U6.1 U6.5 U6.8
copper on no net:
  other v2: 125,125 1875,125 125,2175 1875,2175

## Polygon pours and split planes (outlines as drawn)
VCC on VCC (split plane): 1907.84,2279.61 1915.61,2278.46 1923.22,2276.55 1930.61,2273.91 1937.71,2270.55 1944.44,2266.51 1950.75,2261.84 1956.57,2256.57 1961.84,2250.75 1966.51,2244.44 1970.55,2237.71 1973.91,2230.61 1976.55,2223.22 1978.46,2215.61 1979.61,2207.84 1979.97,2200.63 1979.9,2200 1979.9,100 1979.97,99.37 1979.61,92.16 1978.46,84.39 1976.55,76.78 1973.91,69.39 1970.55,62.29 1966.51,55.56 1961.84,49.25 1956.57,43.43 1950.75,38.16 1944.44,33.49 1937.71,29.45 1930.61,26.09 1923.22,23.45 1915.61,21.54 1907.84,20.39 1900.63,20.03 1900,20.1 100,20.1 99.37,20.03 92.16,20.39 84.39,21.54 76.78,23.45 69.39,26.09 62.29,29.45 55.56,33.49 49.25,38.16 43.43,43.43 38.16,49.25 33.49,55.56 29.45,62.29 26.09,69.39 23.45,76.78 21.54,84.39 20.39,92.16 20.03,99.37 20.1,100 20.1,2200 20.03,2200.63 20.39,2207.84 21.54,2215.61 23.45,2223.22 26.09,2230.61 29.45,2237.71 33.49,2244.44 38.16,2250.75 43.43,2256.57 49.25,2261.84 55.56,2266.51 62.29,2270.55 69.39,2273.91 76.78,2276.55 84.39,2278.46 92.16,2279.61 99.37,2279.97 100,2279.9 1900,2279.9 1900.63,2279.97
GND on GND (split plane): 1907.84,2279.61 1915.61,2278.46 1923.22,2276.55 1930.61,2273.91 1937.71,2270.55 1944.44,2266.51 1950.75,2261.84 1956.57,2256.57 1961.84,2250.75 1966.51,2244.44 1970.55,2237.71 1973.91,2230.61 1976.55,2223.22 1978.46,2215.61 1979.61,2207.84 1979.97,2200.63 1979.9,2200 1979.9,100 1979.97,99.37 1979.61,92.16 1978.46,84.39 1976.55,76.78 1973.91,69.39 1970.55,62.29 1966.51,55.56 1961.84,49.25 1956.57,43.43 1950.75,38.16 1944.44,33.49 1937.71,29.45 1930.61,26.09 1923.22,23.45 1915.61,21.54 1907.84,20.39 1900.63,20.03 1900,20.1 100,20.1 99.37,20.03 92.16,20.39 84.39,21.54 76.78,23.45 69.39,26.09 62.29,29.45 55.56,33.49 49.25,38.16 43.43,43.43 38.16,49.25 33.49,55.56 29.45,62.29 26.09,69.39 23.45,76.78 21.54,84.39 20.39,92.16 20.03,99.37 20.1,100 20.1,2200 20.03,2200.63 20.39,2207.84 21.54,2215.61 23.45,2223.22 26.09,2230.61 29.45,2237.71 33.49,2244.44 38.16,2250.75 43.43,2256.57 49.25,2261.84 55.56,2266.51 62.29,2270.55 69.39,2273.91 76.78,2276.55 84.39,2278.46 92.16,2279.61 99.37,2279.97 100,2279.9 1900,2279.9 1900.63,2279.97
VEE on VEE (split plane): 1907.84,2279.61 1915.61,2278.46 1923.22,2276.55 1930.61,2273.91 1937.71,2270.55 1944.44,2266.51 1950.75,2261.84 1956.57,2256.57 1961.84,2250.75 1966.51,2244.44 1970.55,2237.71 1973.91,2230.61 1976.55,2223.22 1978.46,2215.61 1979.61,2207.84 1979.97,2200.63 1979.9,2200 1979.9,100 1979.97,99.37 1979.61,92.16 1978.46,84.39 1976.55,76.78 1973.91,69.39 1970.55,62.29 1966.51,55.56 1961.84,49.25 1956.57,43.43 1950.75,38.16 1944.44,33.49 1937.71,29.45 1930.61,26.09 1923.22,23.45 1915.61,21.54 1907.84,20.39 1900.63,20.03 1900,20.1 100,20.1 99.37,20.03 92.16,20.39 84.39,21.54 76.78,23.45 69.39,26.09 62.29,29.45 55.56,33.49 49.25,38.16 43.43,43.43 38.16,49.25 33.49,55.56 29.45,62.29 26.09,69.39 23.45,76.78 21.54,84.39 20.39,92.16 20.03,99.37 20.1,100 20.1,2200 20.03,2200.63 20.39,2207.84 21.54,2215.61 23.45,2223.22 26.09,2230.61 29.45,2237.71 33.49,2244.44 38.16,2250.75 43.43,2256.57 49.25,2261.84 55.56,2266.51 62.29,2270.55 69.39,2273.91 76.78,2276.55 84.39,2278.46 92.16,2279.61 99.37,2279.97 100,2279.9 1900,2279.9 1900.63,2279.97
GND on GND 2 (split plane): 1907.84,2279.61 1915.61,2278.46 1923.22,2276.55 1930.61,2273.91 1937.71,2270.55 1944.44,2266.51 1950.75,2261.84 1956.57,2256.57 1961.84,2250.75 1966.51,2244.44 1970.55,2237.71 1973.91,2230.61 1976.55,2223.22 1978.46,2215.61 1979.61,2207.84 1979.97,2200.63 1979.9,2200 1979.9,100 1979.97,99.37 1979.61,92.16 1978.46,84.39 1976.55,76.78 1973.91,69.39 1970.55,62.29 1966.51,55.56 1961.84,49.25 1956.57,43.43 1950.75,38.16 1944.44,33.49 1937.71,29.45 1930.61,26.09 1923.22,23.45 1915.61,21.54 1907.84,20.39 1900.63,20.03 1900,20.1 100,20.1 99.37,20.03 92.16,20.39 84.39,21.54 76.78,23.45 69.39,26.09 62.29,29.45 55.56,33.49 49.25,38.16 43.43,43.43 38.16,49.25 33.49,55.56 29.45,62.29 26.09,69.39 23.45,76.78 21.54,84.39 20.39,92.16 20.03,99.37 20.1,100 20.1,2200 20.03,2200.63 20.39,2207.84 21.54,2215.61 23.45,2223.22 26.09,2230.61 29.45,2237.71 33.49,2244.44 38.16,2250.75 43.43,2256.57 49.25,2261.84 55.56,2266.51 62.29,2270.55 69.39,2273.91 76.78,2276.55 84.39,2278.46 92.16,2279.61 99.37,2279.97 100,2279.9 1900,2279.9 1900.63,2279.97

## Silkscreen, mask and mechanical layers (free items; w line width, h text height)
Top Overlay:
  drawing of 34 lines, arcs and shapes, not listed
  text "AC output channels" at 190,1475 h60 r90
  text "DC output channels" at 1635,1445 h60 r90
  text "LIGO-D2500105-v2 / PD Readout for  / Vigo PVIA-5 / S/N:" at 1960,875 h70 r90
  text "AC MON" at 75,590 h40 r90
  text "DC MON" at 790,590 h40 r90
  text "AC coupling" at 65,405 h60
  text "Transimpedance / amplifier" at 1955,395 h60 r90
  text "+15V" at 813,48 h30
  text "GND" at 958,48 h30
  text "-15V" at 1063,48 h30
